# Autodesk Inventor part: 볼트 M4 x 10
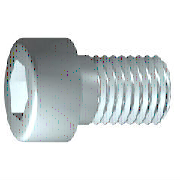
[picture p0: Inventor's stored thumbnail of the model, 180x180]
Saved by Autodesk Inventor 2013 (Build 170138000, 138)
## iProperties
IsCustomPart: 1
Created: 2012-02
Part Number: 볼트 M4 x 10
Material: 강철, 연강
Description: 6각머리 태핑 나사
Document SubType Name: Modeling
Standard: KS B 1003
Designer: mduedu
Standards Organization: KS
Language: ko-KR
Size Designation: M 4 x 10
Categories: <MemberInstance><Categories><Category DisplayName="조임쇠" InternalName="e4da775c-781d-43d5-af7c-5136215cf5a6" Mnemonic="FSTN"><Category DisplayName="볼트" InternalN
Density: 1 g/cm^3
Author: mduedu
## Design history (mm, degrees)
sketch "스케치1"
  geometry: L1 (-1, 0)-(10, 0); L2 (10, 0)-(10, 2); L3 (10, 2)-(1.75, 2); L4 (1.75, 2)-(1.32, 2); L5 (1.32, 2)-(0, 2); L6 (0, 2)-(0, 3.5); L7 (0, 3.5)-(-4, 3.5); L8 (-4, 3.5)-(-4, 1.732); L9 (-4, 1.732)-(-2, 1.732); L10 (-2, 1.732)-(-1, 0); L11 (-6.8, 0)-(12.8, 0) reference; L12 (0, -0.7)-(0, 4.2) reference; L13 (1.75, 2)-(0, 2)
  constraints: 22 end point, 6 parallel, 2 collinear, 2 perpendicular, 1 horizontal, 1 point on line
  dimensions: "d1" = 8.25 distance from line of L3.end L2 (= GEL); "d2" = 0.42952 distance of L4.end L3.end (computed from GAL); "d3" = 4 distance between parallel lines of L8 L6 (= KOH); "d4" = 2 distance of L8.end L9.end (= INTI); "d5" = 60 deg angle of L10 L1; "d6" = 4 diameter of L3 L1 (= GD); "d7" = 4 diameter of L5 L1 (= BDM); "d8" = 3.4641 diameter of L9 L1 (= 1.1547 x SW); "d9" = 7 diameter of L7 L1 (= KOD); "d26" = 10 distance between parallel lines of L12 L2 (= NLG)
revolve "본체" sketch "스케치1" stored, may be unused: angle "d10" = 90 deg
sketch "스케치2"
  geometry: L1 (0, -4.9)-(0, 4.9) reference; L2 (-4.9, 0)-(4.9, 0) reference; L3 (1.732, 0)-(0.866, -1.5); L4 (0.866, -1.5)-(-0.866, -1.5); L5 (-0.866, -1.5)-(-1.732, 0); L6 (-1.732, 0)-(-0.866, 1.5); L7 (-0.866, 1.5)-(0.866, 1.5); L8 (0.866, 1.5)-(1.732, 0); 2 further points
  constraints: 12 end point, 1 coincident, 1 horizontal alignment, 1 point on line, 12 other
extrude "슬롯" join sketch "스케치2" stored distance "d11" = 10; taper "d12" = 0 deg
workplane "Work Plane1"
fillet "Fillet2" dims "d30" = 0.1 (= R)
body "Solid1"
fillet "모깎기1" dims "d17" = 0.4 (= RR)
feature "스레드" dims "d13" = 8.25 (= GEL), "d14" = 0
chamfer "모따기1" distance "d15" = 0.42941 (= -0.5 x SPD + 0.5 x GD); stored, may be unused: second distance "d16" = 0.42941 (= GUL), angle "d27" = 45 deg
other parameters: "GD" = 4 (= NND) [user parameter; used in 2 equation terms], "NLG" = 10 [user parameter; used in 1 equation term], "GEL" = 8.25 [user parameter; used in 2 equation terms], "KOD" = 7 [user parameter; used in 1 equation term], "KOH" = 4 [user parameter; used in 1 equation term], "INTI" = 2 [user parameter; used in 1 equation term], "GAL" = 0.42941 (= 0.61345 x PTC) [user parameter; used in 1 equation term], "GUL" = 0.42941 (= 0.61345 x PTC) [user parameter; used in 1 equation term], "BDM" = 4 (= NND) [user parameter; used in 1 equation term], "SW" = 3 [user parameter; used in 2 equation terms], "RR" = 0.4 [user parameter; used in 1 equation term], "SPD" = 3.14117 (= NND - 1.2269 x PTC) [user parameter; used in 1 equation term], "d19" = 0, "d28" = 0, "d29" = 0, "R" = 0.1 [user parameter; used in 1 equation term], "PHH" = 0.2 [user parameter], "GD1" = 3.14117 (= THREADDIA - 1.2269 x PTC) [user parameter], "THREADDIA" = 4 [user parameter; used in 1 equation term], "FAWI" = 45 deg [user parameter], "TPU" = 14.28571 (computed from PTC) [user parameter], "PTC" = 0.7 [user parameter; used in 5 equation terms], "NND" = 4 [user parameter; used in 3 equation terms], "TOA" = 30 deg [user parameter], "E0" = 3.465 (= 1.155 x SW) [user parameter]
